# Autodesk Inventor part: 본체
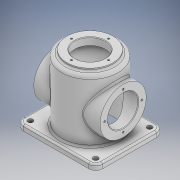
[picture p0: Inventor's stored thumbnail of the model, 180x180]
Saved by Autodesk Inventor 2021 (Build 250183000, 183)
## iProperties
Created: 2021-02
Part Number: 본체
Material: 알루미늄 6061
Document SubType Name: Modeling
Designer: 201-09
Density: 2.7 g/cm^3
Appearance: 기본값
Author: 201-09
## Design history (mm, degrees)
sketch "스케치1"
  geometry: L1 (-70, -60)-(70, -60); L2 (70, -60)-(70, 60); L3 (70, 60)-(-70, 60); L4 (-70, 60)-(-70, -60); L5 (-70, -60)-(70, 60); L6 (70, -60)-(-70, 60); C1 r 42 at (0, 0); 1 further point
  constraints: 12 end point, 2 midpoint, 2 parallel, 1 centre point, 1 coincident, 1 horizontal, 1 perpendicular
  dimensions: "d0" = 140 distance of L3.end L2.end; "d1" = 120 distance of L2.end L1.end; "d7" = 84 diameter of C1
extrude "돌출1" new body sketch "스케치1" distance "d2" = 10; taper "d3" = 0 deg
sketch "스케치2"
  geometry: C1 r 50 at (0, 0); 1 further point
  constraints: 1 centre point, 1 coincident
  dimensions: "d4" = 100 diameter of C1
extrude "돌출2" join sketch "스케치2" distance "d5" = 110; taper "d6" = 0 deg
extrude "돌출3" cut sketch "스케치1" distance "d8" = 112; taper "d9" = 0 deg
sketch "스케치3"
  geometry: C1 r 41 at (0, 0); 1 further point
  constraints: 1 centre point, 1 coincident
  dimensions: "d10" = 82 diameter of C1
extrude "돌출4" join sketch "스케치3" distance "d11" = 5; taper "d12" = 0 deg
sketch "스케치4"
  geometry: C1 r 27 at (0, 0); 1 further point
  constraints: 1 centre point, 1 coincident
  dimensions: "d13" = 54 diameter of C1
extrude "돌출5" cut sketch "스케치4" distance "d14" = 13; taper "d15" = 0 deg
node "작업 평면1"
node "작업 평면2"
sketch "스케치5"
  geometry: L1 (120, -50)-(120, 50) reference; L2 (10, 50)-(10, -50) reference; L3 (10, 50)-(10, -50) reference; L4 (10, -60)-(10, 60) reference; L5 (0, -60)-(0, 60) reference; C1 r 41 at (60, 0); C2 r 27 at (60, 0); A1 r 33 centre (60, 0) between (60, 33) and (93, 0); 5 further points
  constraints: 5 point on circle, 4 horizontal alignment, 3 centre point, 2 coincident, 2 vertical alignment, 1 midpoint
  dimensions: "d18" = 82 diameter of C1; "d19" = 60 distance from line of L5 C1.centre; "d20" = 54 diameter of C2; "d25" = 66 diameter of A1
  node "투영된 루프1"
extrude "돌출6" join sketch "스케치5" stored distance "d21" = 13; taper "d22" = 0 deg
extrude "돌출7" cut sketch "스케치5" stored distance "d23" = 13; taper "d24" = 0 deg
hole "구멍1" sketch "스케치5" diameter "d26" = 3.242; stored, may be unused: countersink angle "d30" = 90 deg, drill point angle "d32" = 118 deg; dims "d27" = 8, "d28" = 4, "d29" = 2, "d31" = 10
sketch "스케치6"
  geometry: C1 r 41 at (0, 0) reference; C2 r 27 at (0, 0) reference; A1 r 33 centre (0, 0) between (0, 33) and (33, 0); 3 further points
  constraints: 4 point on circle, 2 horizontal alignment, 2 vertical alignment, 1 centre point, 1 coincident
  dimensions: "d33" = 66 diameter of A1
hole "구멍2" sketch "스케치6" at (0, 33), (33, 0), (-33, 0), (0, -33) diameter "d34" = 3.242; stored, may be unused: countersink angle "d38" = 90 deg, drill point angle "d40" = 118 deg; dims "d35" = 8, "d36" = 4, "d37" = 2, "d39" = 10
sketch "스케치7"
  geometry: 1 further point
sketch "스케치8"
  geometry: L1 (-70, -60)-(-70, 60) reference; L2 (70, -60)-(-70, -60) reference; L3 (70, 60)-(70, -60) reference; L4 (-70, 60)-(70, 60) reference; C1 r 42 at (0, 0) reference; 1 further point
  node "투영된 루프2"
fillet "모깎기1" dims "d41" = 12
sketch "스케치9"
  geometry: L1 (70, 48)-(70, -48) reference; L2 (-58, 60)-(58, 60) reference; L3 (-70, -48)-(-70, 48) reference; L4 (58, -60)-(-58, -60) reference; C1 r 42 at (0, 0) reference; C2 r 4.5 at (58, 48); C3 r 4.5 at (58, -48); C4 r 4.5 at (-58, -48); C5 r 4.5 at (-58, 48); A1 r 12 centre (58, -48) between (58, -60) and (70, -48) reference; A2 r 12 centre (58, 48) between (70, 48) and (58, 60) reference; A3 r 12 centre (-58, 48) between (-58, 60) and (-70, 48) reference; A4 r 12 centre (-58, -48) between (-70, -48) and (-58, -60) reference; 1 further point
  constraints: 4 centre point, 4 coincident
  dimensions: "d42" = 9 diameter of C2; "d43" = 9 diameter of C3; "d44" = 9 diameter of C4; "d45" = 9 diameter of C5
extrude "돌출8" cut sketch "스케치9" extent not by distance; stored distance "d46" = 0; taper "d47" = 0 deg
fillet "모깎기2" dims "d48" = 3
fillet "모깎기3" dims "d49" = 3
fillet "모깎기4" dims "d50" = 6
fillet "모깎기5" dims "d51" = 3
fillet "모깎기6" dims "d52" = 3
chamfer "모따기1" distance "d53" = 1; stored, may be unused: second distance "d54" = 2, angle "d55" = 45 deg
chamfer "모따기2" distance "d56" = 1; stored, may be unused: second distance "d57" = 2, angle "d58" = 45 deg
chamfer "모따기3" distance "d59" = 1; stored, may be unused: second distance "d60" = 2, angle "d61" = 45 deg
fillet "모깎기7" dims "d62" = 3
node "작업 평면3"
sketch "스케치10"
  geometry: 2 further points
  constraints: 1 other
feature "엠보싱1" sketch "스케치10" dims "d0" = 140, "d1" = 120, "d64" = 0.5, "d65" = 0
node "솔리드1"
mirror "미러1"
node "투영된 루프3"
feature "A9D066F2-1C7D-4E18-AEED-F7BC21143FA4" dims "d26" = 3.242, "d27" = 8, "d28" = 4, "d29" = 2, "d30" = 90 deg, "d31" = 10, "d32" = 118 deg
other parameters: "d16" = -59, "d17" = 59, "d63" = -73.5
